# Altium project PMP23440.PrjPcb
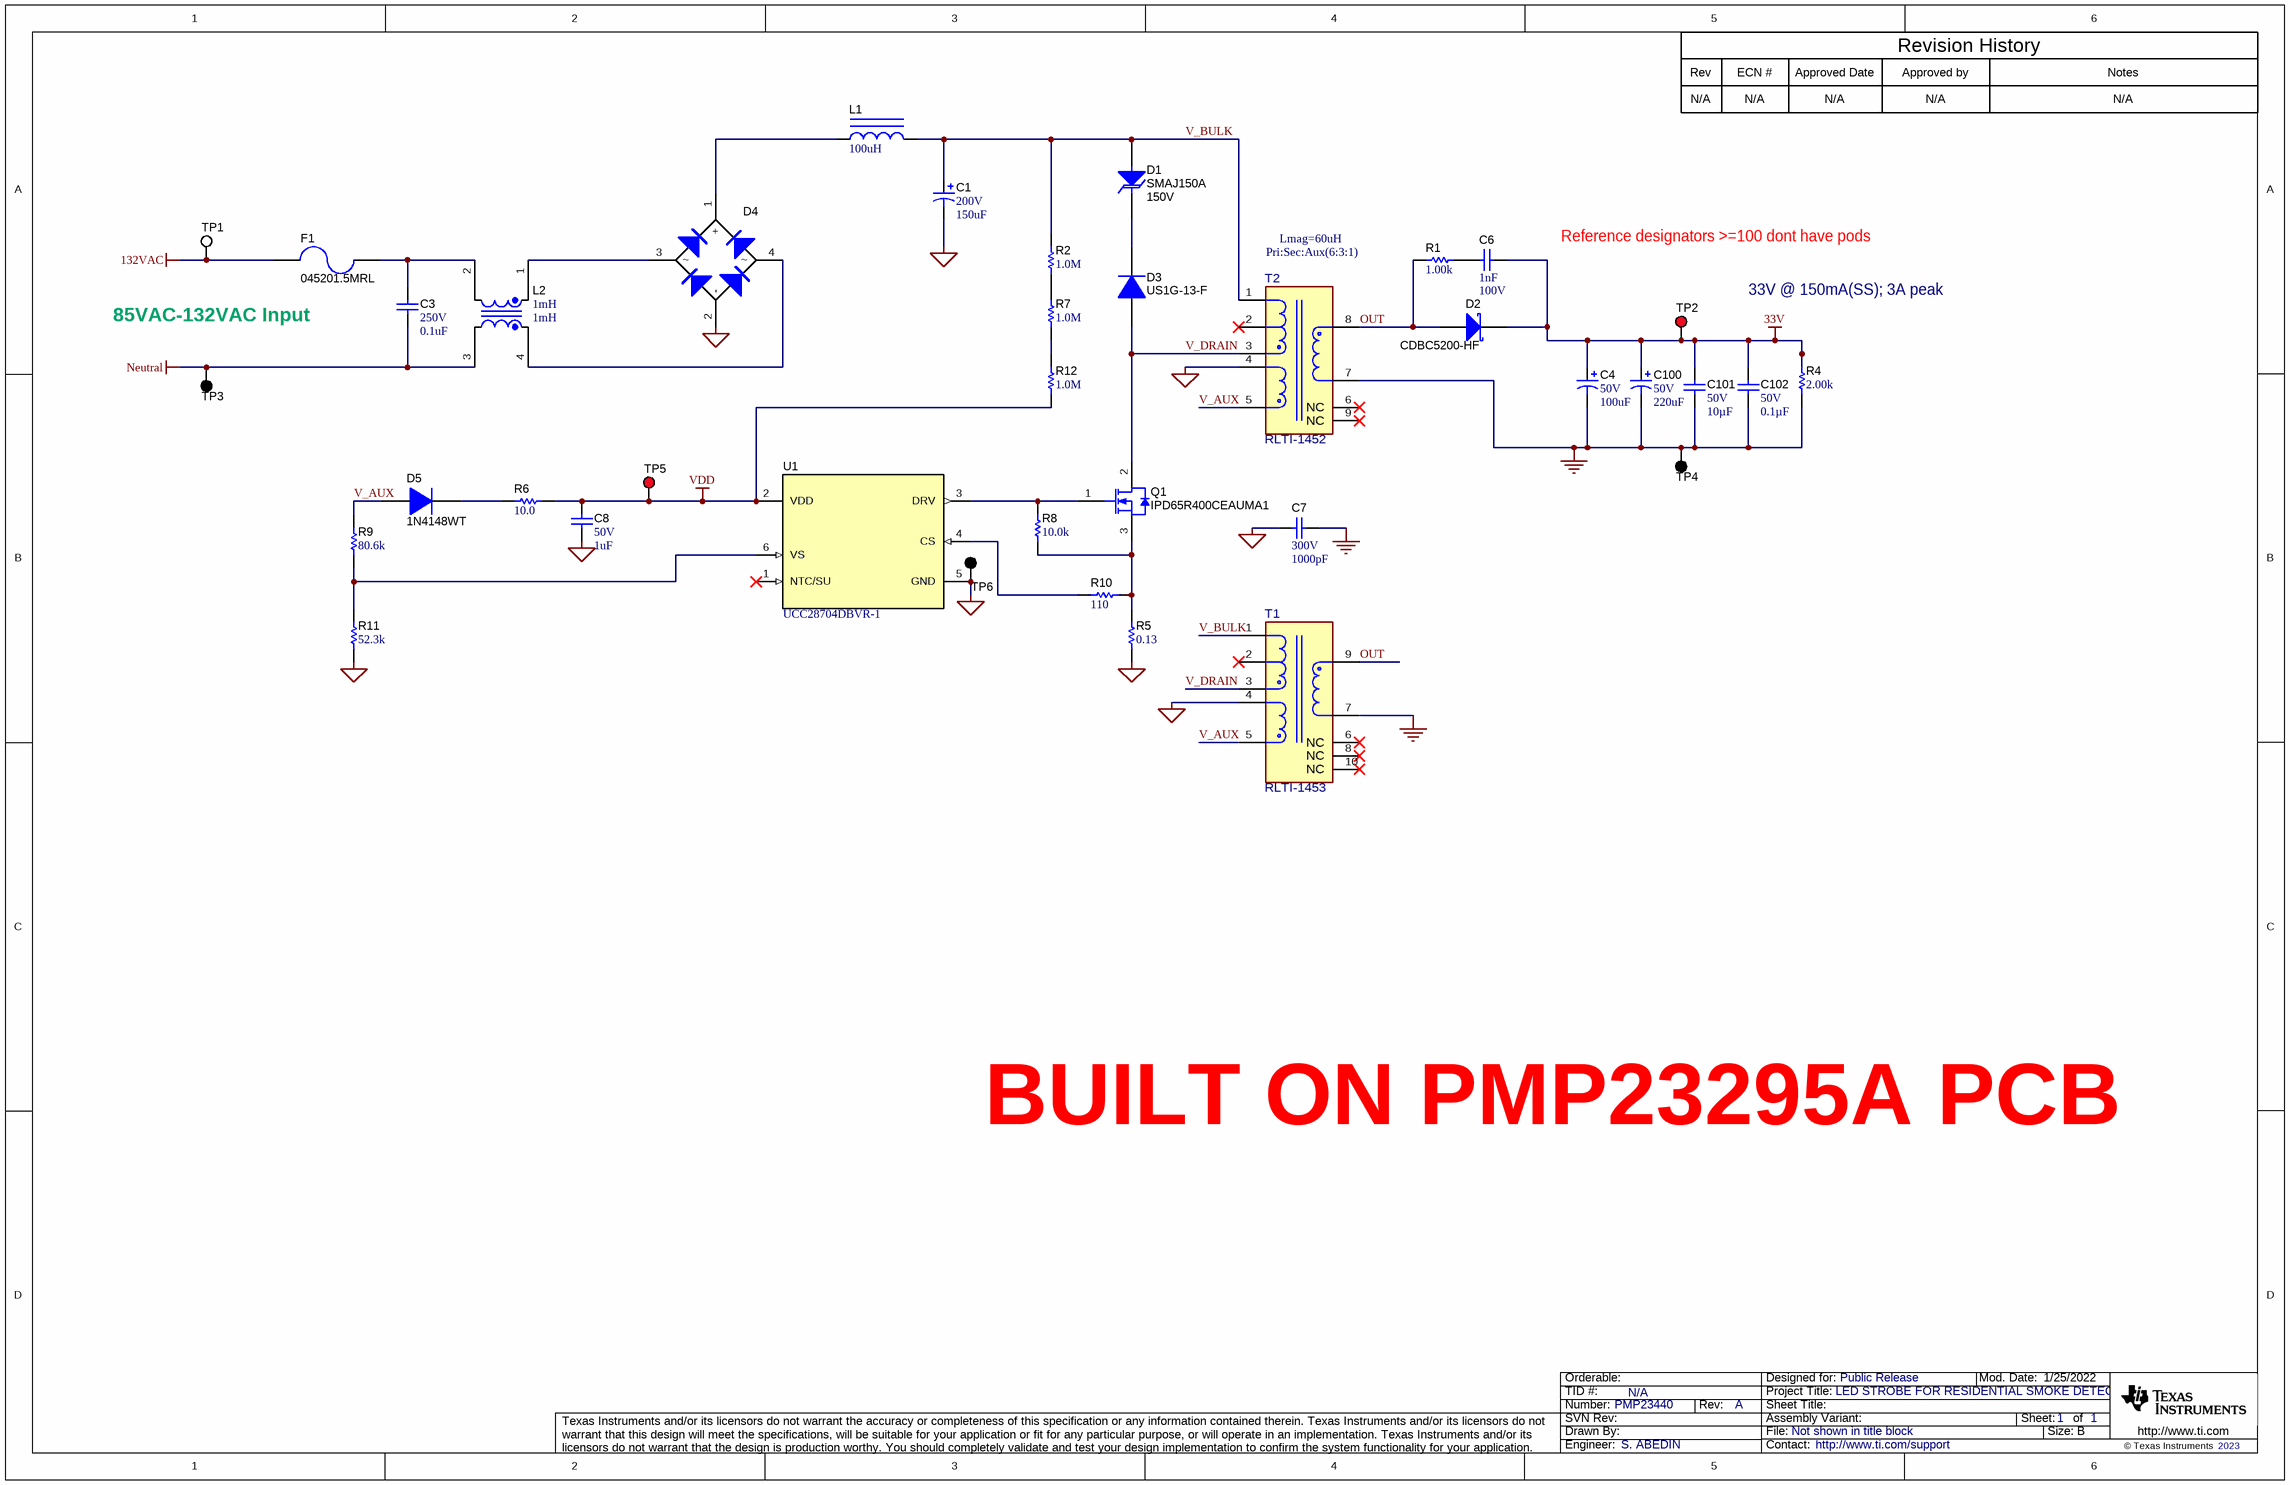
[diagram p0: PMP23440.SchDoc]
TID: N/A; TechSupport: http://www.ti.com/support; SCH_Rev: A; PRJ_Title: LED STROBE FOR RESIDENTIAL SMOKE DETECTOR; PRJ_Number: PMP23440; PRJ_Engineer: S. ABEDIN; PRJ_Customer: Public Release; PCB_Rev: A; PCB_Layout: S. ABEDIN; CopyrightYear: 2023
1 sheet, 38 parts. Net scope: global (net labels, ports and power ports of the same name join across sheets).
Board file: PMP23295.PcbDoc

## Sheet PMP23440.SchDoc
size 431 x 279 mm; Date: Not shown in title block; ApprovedBy: Not shown in title block; CheckedBy: Not shown in title block; Author: Not shown in title block; CompanyName: Not shown in title block; Engineer: Not shown in title block; Organization: Not shown in title block; Address1: Not shown in title block; Address2: Not shown in title block; Address3: Not shown in title block; Address4: Not shown in title block; DocumentNumber: 1; Revision: Use project parameter SCH_Rev; SheetNumber: 1; SheetTotal: 1; PageSetup: Record=PageOptions¦CenterHorizontal=True¦CenterVertical=True¦PrintScale=1.00¦XCorrection=1.00¦YCorrection=1.00¦PrintKind=0¦BorderSize=5000000¦LeftOffset=0¦BottomOffset=0¦Orientation=2¦PaperLength=1000¦PaperWidth=1000¦Scale=100¦PaperSource=15¦PrintQuality=600¦MediaType=1¦DitherType=10¦PaperKind=Letter¦PrintScaleMode=1

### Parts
C1  VDC_V: 200V  ValueDisplayed: 150uF  [CAPPR7.5-16x25]  (hidden comment: EEUED2D151)
C3  VDC_V: 250V  ValueDisplayed: 0.1uF  [R82_720x450x950]  (hidden comment: R82IC3100DQ60J)
C4  VDC_V: 50V  ValueDisplayed: 100uF  [SM_RADIAL_G]  (hidden comment: EEE-FC1H101P)
C6  Cap_F: 1nF  VDC_V: 100V  [0603]  (hidden comment: 06031C102MAT2A)
C7  VDC_V: 300V  ValueDisplayed: 1000pF  [CAPRD750W60D750H1050]  (hidden comment: VY2102M29Y5UG63V7)
C8  VDC_V: 50V  ValueDisplayed: 1uF  [0603]  (hidden comment: C1608X5R1H105K080AB)
C100  VDC_V: 50V  ValueDisplayed: 220uF  [Chemi-Con_1000x1600]  (hidden comment: EKZE500ELL221MJ16S)
C101  VDC_V: 50V  ValueDisplayed: 10µF  [1210_280]  (hidden comment: GRJ32ER71H106KE11L)
C102  VDC_V: 50V  ValueDisplayed: 0.1µF  [0402]  (hidden comment: UMK105B7104MV-FR)
D1  SMAJ150A  value 150V  [SMA]
D2  CDBC5200-HF  [SMC]
D3  US1G-13-F  [SMA]
D4  HD02-T  [MiniDIP]  (value not drawn)
D5  1N4148WT  [Fairchild_SOD-523F]
F1  045201.5MRL  [SloBlo452]
L1  ValueDisplayed: 100uH  [DR74]  (hidden comment: DR74-101-R)
L2  value 1mH  [WE-CMB_XS]  (hidden comment: 744821201)
Q1  IPD65R400CEAUMA1  [DPAK]
R1  ValueDisplayed: 1.00k  [0805_HV]  (hidden comment: RP73PF2A1K0BTDF)
R2  ValueDisplayed: 1.0M  [0805_HV]  (hidden comment: CRCW08051M00JNEA)
R4  ValueDisplayed: 2.00k  [1206]  (hidden comment: RP73D2B2K0BTG)
R5  ValueDisplayed: 0.13  [1210]  (hidden comment: MCR25JZHFLR150)
R6  ValueDisplayed: 10.0  [0805_HV]  (hidden comment: RC0805FR-0710RL)
R7  ValueDisplayed: 1.0M  [0805_HV]  (hidden comment: CRCW08051M00JNEA)
R8  ValueDisplayed: 10.0k  [0402S]  (hidden comment: MCS0402MD1002BE100)
R9  ValueDisplayed: 80.6k  [1206]  (hidden comment: CRCW120680K6FKEA)
R10  ValueDisplayed: 110  [0402]  (hidden comment: CRCW0402110RFKED)
R11  ValueDisplayed: 52.3k  [0603]  (hidden comment: RT0603DRE0752K3L)
R12  ValueDisplayed: 1.0M  [0805_HV]  (hidden comment: CRCW08051M00JNEA)
T1  RLTI-1453  [FP-RLTI-1453_SMT10_0IN85_0IN80-MFG]
T2  RLTI-1452  [FP-RLTI-1452_SMT9_0IN75_0IN93-MFG]
TP1  5012  [Keystone5012]  (value not drawn)
TP2  5010  [Keystone5010]  (value not drawn)
TP3  5011  [Keystone5011]  (value not drawn)
TP4  5011  [Keystone5011]  (value not drawn)
TP5  5010  [Keystone5010]  (value not drawn)
TP6  5011  [Keystone5011]  (value not drawn)
U1  UCC28704DBVR-1  [DBV0006A_N]

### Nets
33V: C4.1(+) C6.1 C100.1(+) C101.1 C102.1 D2.1(K) R4.2 TP2.1
132VAC: F1.2 TP1.1
Neutral: C3.2 L2.3 TP3.1
PGND: C1.2(-) C7.2 C8.2 D4.2(-) R5.1 R11.1 T1.4(PGND) T2.4(PGND) TP6.1 U1.5(GND)
RTN: C4.2(-) C7.1 C100.2(-) C101.2 C102.2 R4.1 T1.7(SGND) T2.7(SGND) TP4.1
VDD: C8.1 R6.2 R12.1 TP5.1 U1.2(VDD)
OUT: D2.2(A) R1.1 T1.9(33V) T2.8(33V)
V_AUX: D5.2(A) R9.2 T1.5(VCC) T2.5(VCC)
V_BULK: C1.1(+) D1.2(A) L1.2 R2.2 T1.1(VDC+) T2.1(VDC+)
V_DRAIN: D3.2(A) Q1.2(D) T1.3(VDRAIN) T2.3(VDRAIN)
NetC3_1: C3.1 F1.1 L2.2
NetC6_2: C6.2 R1.2
NetD1_1: D1.1(K) D3.1(K)
NetD4_1: D4.1(+) L1.1
NetD4_3: D4.3 L2.1
NetD4_4: D4.4 L2.4
NetD5_1: D5.1(K) R6.1
NetQ1_1: Q1.1(G) R8.2 U1.3(DRV)
NetQ1_3: Q1.3(S) R5.2 R8.1 R10.2
NetR2_1: R2.1 R7.2
NetR7_1: R7.1 R12.2
NetR9_1: R9.1 R11.2 U1.6(VS)
NetR10_1: R10.1 U1.4(CS)

Not connected (* = marked no-connect by the designer): T1 2* 6(NC)* 8(NC)* 10(NC)*; T2 2* 6(NC)* 9(NC)*; U1 1(NTC/SU)*

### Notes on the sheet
- Rev
- N/A
- ECN #
- Approved Date
- Approved by
- Revision History
- Notes
- Pri:Sec:Aux(6:3:1)
- Lmag=60uH
- Reference designators >=100 dont have pods
- 33V @ 150mA(SS); 3A peak
- 85VAC-132VAC Input
- BUILT ON PMP23295A PCB

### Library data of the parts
C1 = CMP-0010012-2: CAP, AL, 150 uF, 200 V, +/- 20%, 0.16247 ohm, TH; Manufacturer: Panasonic; TaMin_C: -25°C; ESR_ohm: 0.1625; Polarized: Y; SizeAreaWB_mm2: 324; U/M: EA; Value: 150uF; TaMax_C: 105°C; SizeZ_mm: 25; SizeX_mm: 16; AC_Derating: 0.35; SizeArea_mm2: 256; CompType: Capacitor; Cap_F: 150µF; IRMS_A: 1.4A; AEC Category: Q200
C3 = CMP-0012568-2: CAP, Film, 0.1 uF, 250 V, +/- 5%, TH; Manufacturer: Kemet; TaMin_C: -55°C; Polarized: N; Value1: Unknown; U/M: EA; Value: 0.1uF; TaMax_C: 105°C; Cap_Case: 7.2x4.5x9.5mm; Cap_F: 100nF; AEC Category: Q200
C4 = CMP-0011166-1: CAP, AL, 100 uF, 50 V, +/- 20%, 0.3 ohm, SMD; Manufacturer: Panasonic; TaMin_C: -40°C; ESR_ohm: 0.3; Polarized: Y; SizeAreaWB_mm2: 172.2; Value1: 0.3 ohm; U/M: EA; Value: 100uF; TaMax_C: 105°C; SizeZ_mm: 10.2; SizeX_mm: 12; SizeY_mm: 10.3; Cap_Case: G; SizeArea_mm2: 123.6; CompType: Capacitor; Cap_F: 100µF; IRMS_A: 500mA; AEC Category: Q200
C6 = CMP-0006725-3: CAP, CERM, 1000 pF, 100 V, +/- 20%, X7R, 0603; Manufacturer: AVX; TaMin_C: -55°C; ESR_ohm: 0.276; Polarized: N; SizeAreaWB_mm2: 4.68; Value1: 0.276 ohm; U/M: EA; Value: 1000pF; TaMax_C: 125°C; SizeZ_mm: 1; SizeX_mm: 1.6; SizeY_mm: 0.8; SizeArea_mm2: 1.28; AEC Category: Q200
C7 = CMP-0009625-1: CAP, CERM, 1000 pF, 300 V, +/- 20%, Y5U, Radial Disc 7.5mm, ls=7.5; Manufacturer: Vishay-Bccomponents; TaMin_C: -40°C; Polarized: N; SizeAreaWB_mm2: 72.1; Value1: Unknown; U/M: EA; Value: 1000pF; TaMax_C: 125°C; SizeZ_mm: 11.5; SizeX_mm: 8.3; SizeY_mm: 5; SizeArea_mm2: 41.5; Cap_F: 1nF; AEC Category: Q200
C8 = CMP-0007011-2: CAP, CERM, 1 uF, 50 V, +/- 10%, X5R, 0603; Manufacturer: TDK; TaMin_C: -55°C; ESR_ohm: 5.522m; Polarized: N; SizeAreaWB_mm2: 4.68; Value1: 0.005522 ohm; U/M: EA; Value: 1uF; TaMax_C: 85°C; SizeZ_mm: 1; SizeX_mm: 1.6; SizeY_mm: 0.8; SizeArea_mm2: 1.28; Cap_F: 1µF; IRMS_A: 2.2162A; AEC Category: Q200
C100 = CMP-0009885-2: CAP, AL, 220 uF, 50 V, +/- 20%, TH; Manufacturer: Chemi-Con; TaMin_C: -40°C; Polarized: Y; SizeAreaWB_mm2: 144; Value1: Unknown; U/M: EA; Value: 220uF; TaMax_C: 105°C; SizeZ_mm: 17.5; SizeX_mm: 10; Cap_Case: 10x16; SizeArea_mm2: 100; CompType: Capacitor; AEC Qualified: N; Cap_F: 220µF; IRMS_A: 1.37A; AEC Category: Q200
C101 = CMP-0081135-1: CAP, CERM, 10 µF, 50 V,+/- 10%, X7R, 1210; Manufacturer: MuRata; TaMin_C: -55°C; ESR_ohm: 1m; Polarized: N; SizeAreaWB_mm2: 14.7; Value1: 0.001 ohm; U/M: EA; Value: 10uF; TaMax_C: 125°C; SizeZ_mm: 2.8; SizeX_mm: 3.2; SizeY_mm: 2.5; Cap_Case: 1210; SizeArea_mm2: 8; AEC Category: Q200
C102 = CMP-0860570-1: CAP, CERM, 0.1 µF, 50 V,+/- 20%, X7R, 0402; Manufacturer: Taiyo Yuden; SizeAreaWB_mm2: 3; SizeZ_mm: 0.6; TaMax_C: 125°C; SizeY_mm: 0.5; TaMin_C: -55°C; Cap_F: 100nF; AEC Category: Q200; U/M: EA; SizeX_mm: 1; Value: 0.1uF; Polarized: N
D1 = CMP-0084982-1: Diode, TVS, Uni, 150 V, 243 Vc, 400 W, 1.6 A, SMA; Manufacturer: Littelfuse; Vc: 243V; Ipp: 1.6A; RJA_CperW: 120; AEC Qualified: N; Ppk: 400W; AEC Category: Q101; SizeArea_mm2: 16.3228; SizeAreaWB_mm2: 37.3428; SizeZ_mm: 2.87; Vbr_Max: 185V; SizeX_mm: 5.59; SizeY_mm: 2.92; Vbr_Min: 167V
D2 = CMP-0077804-2: Diode, Schottky, 200 V, 5 A, SMC; Manufacturer: Comchip Technology; Value1: 5A; TJmax_C: 175°C; Vr_V: 200V; AEC Category: Q101; AEC Qualified: N; SizeAreaWB_mm2: 83.2686; Value: 200V; SizeX_mm: 8.13; Vf_V: 900mV; SizeZ_mm: 2.6; SizeY_mm: 6.22; SizeArea_mm2: 50.5686; Value2: 0.9V
D3 = CMP-0077026-1: Diode, Ultrafast, 400 V, 1 A, SMA; Manufacturer: Diodes Inc.; SizeAreaWB_mm2: 37.3428; Vr_V: 400V; SizeArea_mm2: 16.3228; TJmax_C: 150°C; AEC Category: Q101; Value: 400V; SizeZ_mm: 2.87; Green_REACh: Incomplete; Io_A: 1A; Vf_V: 1.3V; SizeY_mm: 2.92; Green_Lifecycle: Not Set; U/M: EA; SizeX_mm: 5.59
D4 = CMP-0029216-2: Diode, Switching-Bridge, 200 V, 0.8 A, MiniDIP; Manufacturer: Diodes Inc.; Io_A: 800mA; Green_Lifecycle: Not Set; SizeAreaWB_mm2: 62.1; Vr_V: 200V; Green_REACh: Incomplete; Value1: 0.8A; TJmax_C: 150°C; U/M: EA; Value: 200V; SizeZ_mm: 3; SizeX_mm: 7; SizeY_mm: 4.9; Vf_V: 1V; SizeArea_mm2: 34.3; AEC Category: Q101
D5 = CMP-0076982-2: Diode, Switching, 75 V, 0.3 A, SOD-523F; Manufacturer: Fairchild Semiconductor; TJmax_C: 150°C; AEC Category: Q101; SizeX_mm: 1.6; Value: 75V; Io_A: 300mA; Value1: 0.3A; Green_REACh: Incomplete; SizeZ_mm: 0.7; Green_Lifecycle: Not Set; SizeArea_mm2: 1.28; SizeAreaWB_mm2: 4.68; SizeY_mm: 0.8
F1 = CMP-0003477-2: Fuse, 1.5 A, 125VAC/VDC, SMD; Manufacturer: Littelfuse; Irating_A: 1.5A; Interrupt_AC: 50A; VAC_V: 125V; Rtyp_Ohm: 93m; MeltingTyp: 3.65
L1 = CMP-0058224-1: Inductor, Shielded Drum Core, Ferrite, 100 uH, 0.86 A, 0.383 ohm, SMD; Manufacturer: Coiltronics; Isat: 0.99A @ 30% inductance drop; Irms: 0.86A @ 40C rise; Green_Lifecycle: Not Set; SizeAreaWB_mm2: 92.16; DCR_ohm: 0.383; Green_REACh: Incomplete; Value: 100uH; Imax_A: 860mA; SizeZ_mm: 4.35; SizeX_mm: 7.6; Value2: 0.86A; SizeArea_mm2: 57.76; Ind_H: 100µH; AEC Category: Q200
L2 = CMP-0013113-1: Coupled inductor, 1 mH, 2 A, 0.045 ohm, TH; Manufacturer: Wurth Elektronik; SizeAreaWB_mm2: 161.5; DCR_ohm: 45m; SizeZ_mm: 20.5; SizeX_mm: 15; SizeY_mm: 7.5; SizeArea_mm2: 112.5
Q1 = CMP-0001129-3: MOSFET, N-CH, 550 V, 13 A, DPAK; Alternate Manufacturer: None; Manufacturer: Infineon Technologies; VdsMax_V: 550V; ChMode: Enhancement; Value: 550V; SizeY_mm: 6.54; Value2: 32.6 nC; SizeZ_mm: 2.29; SizeX_mm: 9.91; SizeAreaWB_mm2: 101.7114; IdsMax_A: 13A; Vgs_V: 30V; ChType: N; SizeArea_mm2: 64.8114; AEC Category: Q101; QgTyp_nC: 32.6
R1 = CMP-0019089-1: RES, 1.00 k, 0.1%, 0.25 W, 0805; Manufacturer: TE Connectivity; Power_W: 250mW; TempCo: 25 ppm/C; Value_Code: 1k00; U/M: EA; Value: 1.00k; EIA_Code: E192; Res_ohm: 1k; SizeX_mm: 2; SizeY_mm: 1.25; SizeZ_mm: 1.45; Value2: 0.25W; SizeArea_mm2: 2.5; VDC_V: 150V; AEC Category: Q200
R2 R7 R12 = CMP-0020480-2: RES, 1.0 M, 5%, 0.125 W, 0805; Manufacturer: Vishay-Dale; Power_W: 125mW; TempCo: 200 ppm/C; Value_Code: 1M00; U/M: EA; Value: 1.0Meg; EIA_Code: E24; Res_ohm: 1M; SizeX_mm: 2; SizeY_mm: 1.25; SizeZ_mm: 1.45; Value2: 0.125W; SizeArea_mm2: 2.5; VDC_V: 150V; AEC Category: Q200
R4 = CMP-0018798-2: RES, 2.00 k, 0.1%, 0.25 W, 1206; Manufacturer: TE Connectivity; Power_W: 250mW; TempCo: 15 ppm/C; Value_Code: 2k00; U/M: EA; Value: 2.00k; EIA_Code: E192; Res_ohm: 2k; SizeX_mm: 3.2; SizeY_mm: 1.6; SizeZ_mm: 1.35; Value2: 0.25W; SizeArea_mm2: 5.12; AEC Qualified: N; VDC_V: 200V; AEC Category: Q200
R5 = CMP-0015171-2: RES, 0.15, 1%, 0.5 W, 1210; Manufacturer: Rohm; Power_W: 500mW; TempCo: 200 ppm/C; SizeAreaWB_mm2: 14.7; Value_Code: R150; U/M: EA; Value: 0.15; EIA_Code: E96; SizeX_mm: 3.2; SizeY_mm: 2.5; SizeZ_mm: 1.35; Value2: 0.5W; SizeArea_mm2: 8; VDC_V: 0V; AEC Category: Q200
R6 = CMP-0021863-1: RES, 10.0, 1%, 0.125 W, 0805; Manufacturer: Yageo America; Power_W: 125mW; TempCo: 200 ppm/C; Value_Code: 10R0; U/M: EA; Value: 10.0; EIA_Code: E96; Res_ohm: 10; SizeX_mm: 2; SizeY_mm: 1.25; SizeZ_mm: 1.45; Value2: 0.125W; SizeArea_mm2: 2.5; VDC_V: 150V; AEC Category: Q200
R8 = CMP-0077124-1: RES, 10.0 k, 0.1%, 0.1 W, AEC-Q200 Grade 0, 0402; Manufacturer: Vishay/Beyschlag; Value_Code: 10k0; SizeArea_mm2: 0.5; AEC Qualified: Y; AEC Category: Q200; Res_ohm: 10k; Value: 10.0k; SizeZ_mm: 0.6; EIA_Code: E192; TempCo: 25 ppm/C; AEC Grade: 0; Power_W: 100mW; VDC_V: 50V; Value2: 0.1W; U/M: EA; SizeX_mm: 1.0
R9 = CMP-0017185-2: RES, 80.6 k, 1%, 0.25 W, 1206; Manufacturer: Vishay-Dale; Power_W: 250mW; TempCo: 100 ppm/C; Value_Code: 80k6; U/M: EA; Value: 80.6k; EIA_Code: E96; SizeX_mm: 3.2; SizeY_mm: 1.6; SizeZ_mm: 1.35; Value2: 0.25W; SizeArea_mm2: 5.12; VDC_V: 200V; AEC Category: Q200
R10 = CMP-0025968-2: RES, 110, 1%, 0.063 W, 0402; Manufacturer: Vishay-Dale; Power_W: 63mW; TempCo: 100 ppm/C; Value_Code: 110R; U/M: EA; Value: 110; EIA_Code: E96; SizeX_mm: 1; SizeY_mm: 0.5; SizeZ_mm: 0.6; Value2: 0.063W; VDC_V: 50V; AEC Category: Q200
R11 = CMP-0025387-2: RES, 52.3 k, 0.5%, 0.1 W, 0603; Manufacturer: Yageo America; Power_W: 100mW; TempCo: 50 ppm/C; Value_Code: 52k3; U/M: EA; Value: 52.3k; EIA_Code: E192; SizeX_mm: 1.6; SizeY_mm: 0.8; SizeZ_mm: 1; Value2: 0.1W; SizeArea_mm2: 1.28; VDC_V: 75V; AEC Category: Q200
T1 = CMP-0096939-1: Transformer Flyback (EFD20) for PMP23925; Manufacturer: Renco Electronics; DCR_ohm: 3.1; Voltage_Isolation_Vrms: 1.5kV; SizeZ_mm: 0.4inch; Ns1toNp: 1:0.333/1:0.092; AEC Qualified: No; Ind_H: 350µH; Rsec1_ohm: 0.42
T2 = CMP-0096938-1: Transformer Flyback (EPC17) for PMP23925; Manufacturer: Renco Electronics; Rsec1_ohm: 0.55; DCR_ohm: 4; SizeZ_mm: 0.425inch; AEC Qualified: No; Ns1toNp: 1:0.335/1:0.09; Ind_H: 350µH; Voltage_Isolation_Vrms: 1.5kV
TP1 = CMP-0055149-1: Test Point, Multipurpose, White, TH; Manufacturer: Keystone; CNHeader: FALSE; Green_Lifecycle: Active; Green_REACh: Passed; ContactFinish: Silver; CT: TRUE
TP2 TP5 = CMP-0055147-1: Test Point, Multipurpose, Red, TH; Manufacturer: Keystone; CNHeader: FALSE; Green_Lifecycle: Active; Green_REACh: Passed; ContactFinish: Silver; CT: TRUE
TP3 TP4 TP6 = CMP-0055148-1: Test Point, Multipurpose, Black, TH; Manufacturer: Keystone; CNHeader: FALSE; Green_Lifecycle: Active; Green_REACh: Passed; ContactFinish: Silver; CT: TRUE
U1 = CMP-0074087-1: Off-Line Constant-Voltage Constant-Current Flyback Controller With Primary-Side Regulation (PSR), DBV0006A (SOT-23-6); Alternate PartNumber: UCC28704DBVT-1; Alternate Manufacturer: Texas Instruments; Green_Lifecycle: Active; SizeAreaWB_mm2: 14.82; Green_REACh: Passed; U/M: EA; SizeZ_mm: 1.45; SizeX_mm: 2.8; SizeY_mm: 2.9; SizeArea_mm2: 8.12; CompType: IC

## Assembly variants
001: not fitted C6 R1 T1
